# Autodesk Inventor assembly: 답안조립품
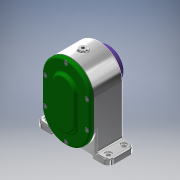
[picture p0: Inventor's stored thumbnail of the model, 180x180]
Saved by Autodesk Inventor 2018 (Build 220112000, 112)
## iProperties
Created: 2021-05
Part Number: 답안조립품
Material: 일반
Document SubType Name: Assembly
Designer: admin
Author: admin
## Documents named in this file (19)
- C:\Users\admin\Desktop\710509V1003\답안조립품.iam
- C:\Users\admin\Desktop\710509V1003\부품.ipt
- C:\Users\admin\Desktop\710509V1003\710509V1003\베어링 6001.ipt
- 베어링 6001.ipt
- C:\Users\admin\Desktop\710509V1003\710509V1003\축 A.ipt
- C:\Users\admin\Desktop\710509V1003\710509V1003\축 B.ipt
- C:\Users\admin\Desktop\710509V1003\710509V1003\칼라.ipt
- C:\Users\admin\Desktop\710509V1003\710509V1003\커버 B.ipt
- C:\Users\admin\Desktop\710509V1003\710509V1003\개스킷 B.ipt
- C:\Users\admin\Desktop\710509V1003\710509V1003\오일 실 12 22 7.ipt
- C:\Users\admin\Desktop\710509V1003\710509V1003\베어링 6002.ipt
- 베어링 6002.ipt
- C:\Users\admin\Desktop\710509V1003\710509V1003\개스킷 A.ipt
- C:\Users\admin\Desktop\710509V1003\710509V1003\커버 A.ipt
- C:\Users\admin\Desktop\710509V1003\710509V1003\키 5 x 5 x 12.ipt
- C:\Users\admin\Desktop\710509V1003\710509V1003\키 4 x 4 x 12.ipt
- C:\Users\admin\Desktop\710509V1003\710509V1003\스퍼기어 A.ipt
- C:\Users\admin\Desktop\710509V1003\710509V1003\스퍼기어 B.ipt
- C:\Users\admin\Desktop\710509V1003\710509V1003\볼트 M4.ipt
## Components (2 placed, 2 different names)
1. 개스킷 B:1
2. 개스킷 A:1
